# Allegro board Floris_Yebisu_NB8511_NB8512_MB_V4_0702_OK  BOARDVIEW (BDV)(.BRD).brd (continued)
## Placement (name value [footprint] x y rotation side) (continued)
CT28  cap  [C0201]  22.17 27.63 180 top
CT29  cap  [C0201]  24.26 27.63 0 top
CT30  CAP  [C0201]  25.91 23.44 90 bottom
CT31  CAP  [C0201]  31.37 24.58 0 top
CT32  CL10A226MQ8NRNC~~GRM188R60J226MEA0D~~JDK107BBJ226MA-T~~CC0603MRX5R5BB226  [C0603_L]  28.19 28.39 90 top
CT33  CL10A226MQ8NRNC~~GRM188R60J226MEA0D~~JDK107BBJ226MA-T~~CC0603MRX5R5BB226  [C0603_L]  29.49 28.39 90 top
CT34  CAP  [C0201]  29.06 29.08 180 bottom
CT35  CAP  [C0201]  29.06 28.57 180 bottom
CT36  CAP  [C0201]  24.36 22.55 180 bottom
CT37  CAP  [C0201]  27.76 24.97 0 bottom
CT38  CL10A226MQ8NRNC~~GRM188R60J226MEA0D~~JDK107BBJ226MA-T~~CC0603MRX5R5BB226  [C0603_L]  32.89 28.39 90 top
CT39  CL10A226MQ8NRNC~~GRM188R60J226MEA0D~~JDK107BBJ226MA-T~~CC0603MRX5R5BB226  [C0603_L]  31.49 28.39 90 top
CT40  CAP  [C0201]  31.62 28.27 90 bottom
CT41  CAP  [C0201]  27.73 22.78 0 bottom
CT42  CAP  [C0201]  25.14 23.95 180 bottom
CT43  CAP  [C0201]  23.11 23.95 180 bottom
CT44  CAP  [C0201]  32.13 28.27 90 bottom
CT45  CAP  [C0201]  27.56 24.2 270 bottom
CT46  C0201C0G180J500NTA~~GRM0335C1H180JA01D~~CC0201JRNPO9BN180  [C0201]  27.73 23.34 0 bottom
CT47  CAP  [C0201]  26.31 28.22 90 top
CT48  C0402X5R106M6R3NTC~~CL05A106MQ5NUNC~~GRM155R60J106ME44~~JMK105CBJ106MV-F  [C0402_0D8]  27.05 28.37 90 top
CT50  CAP  [C0201]  24.13 26.29 180 bottom
CT51  C0201C0G180J500NTA~~GRM0335C1H180JA01D~~CC0201JRNPO9BN180  [C0201]  24.13 25.73 180 bottom
CT52  C0402X5R106M6R3NTC~~CL05A106MQ5NUNC~~GRM155R60J106ME44~~JMK105CBJ106MV-F  [C0402_0D8]  25.78 28.78 90 bottom
CT54  C0201X5R104M6R3NTA~~0201X104M6R3NT  [C0201]  24.51 32.71 0 bottom
CT55  C0402X5R475M6R3NTC~~JMK105BBJ475MV-F+JDK105ABJ475MV~~CC0402MRX5R5BB475~~CL05A475MQ5NRNC~~GRM155R60J475ME87D  [C0402_0D65]  24.74 12.11 270 top
CT56  C0201X5R104M250NTJ  [C0201]  23.98 12.11 270 top
CT57  PSBD1DF40V3H  [DIODE_2D75X1D8X1D1]  19.66 15.39 0 top
CT58  C0603X5R106M250NTK~~CL10A106MA8NRNC~~GRM188R61E106MA73D~~TMK107BBJ106MA  [C0603_L]  25.91 12.16 270 top
CT59  C0603X5R106M250NTK~~CL10A106MA8NRNC~~GRM188R61E106MA73D~~TMK107BBJ106MA  [C0603_L]  27.28 12.16 270 top
CT60  C0603X5R106M250NTK~~CL10A106MA8NRNC~~GRM188R61E106MA73D~~TMK107BBJ106MA  [C0603_L]  18.54 12.27 270 top
CT61  C0201X7R102K250NTA+C0201X7R102K250NJA~~GRM033R71E102KA01D~~CC0201KRX7R8BB102  [C0201]  20.06 9.48 180 top
CT62  xxxxxx  [C0402]  12.7 22.93 180 bottom
CT63  xxxxxx  [C0402]  12.7 22.04 180 bottom
CT64  xxxxxx  [C0402]  12.44 16.96 180 top
CT65  xxxxxx  [C0402]  12.44 17.85 180 top
CT66  C0201X5R104M250NTJ  [C0201]  8.89 11.88 180 top
CT67  C0201X5R105M6R3NTX~~CL03A105MQ3CSNH~~GRM033R60J105MEA2D~~JMK063ABJ105MP+JDK063ABJ105MP~~CC0201MRX5R5BB105  [C0201_0D4]  13.84 8.2 0 top
CT68  xxxxxx  [C0402]  12.7 22.93 180 top
CT69  xxxxxx  [C0402]  12.7 22.04 180 top
CT70  xxxxxx  [C0402]  12.44 16.96 180 bottom
CT71  xxxxxx  [C0402]  12.44 17.85 180 bottom
CT72  C0201C0G101J500NTA~~GRM0335C1H101JA01D~~CC0201JRNPO9BN101  [C0201]  9.29 11.17 90 bottom
CT73  C0201C0G101J500NTA~~GRM0335C1H101JA01D~~CC0201JRNPO9BN101  [C0201]  9.29 10.13 270 bottom
CT74  C0201X5R104M250NTJ  [C0201]  11.12 14.42 270 top
CT75  C0603X5R106M250NTK~~CL10A106MA8NRNC~~GRM188R61E106MA73D~~TMK107BBJ106MA  [C0603_L]  13.59 14.3 270 top
CT76  C0201X5R104M250NTJ  [C0201]  12.65 14.42 270 top
CT77  C0603X5R106M250NTK~~CL10A106MA8NRNC~~GRM188R61E106MA73D~~TMK107BBJ106MA  [C0603_L]  14.88 14.3 270 top
CT78  C0201C0G470J250NTA~~GRM0335C1E470JD01D~~CC0201JRNPO8BN470  [C0201]  12.14 14.42 270 top
CT79  C0201C0G101J500NTA~~GRM0335C1H101JA01D~~CC0201JRNPO9BN101  [C0201]  10.31 8.63 0 bottom
CT80  C0201C0G101J500NTA~~GRM0335C1H101JA01D~~CC0201JRNPO9BN101  [C0201]  8.33 8.71 90 bottom
CT81  CC0201JRNPO9BN220~~C0201C0G220J500NTA  [C0201]  11.63 14.42 270 top
CT82  CL10A226MQ8NRNC~~GRM188R60J226MEA0D~~JDK107BBJ226MA-T~~CC0603MRX5R5BB226  [C0603_L]  34.44 26.13 0 top
CT83  CL10A226MQ8NRNC~~GRM188R60J226MEA0D~~JDK107BBJ226MA-T~~CC0603MRX5R5BB226  [C0603_L]  34.29 28.39 90 top
CU1  CC0201JRNPO8BN220~~GRM0335C1E220JD01  [C0201]  72.01 72.84 90 top
CU2  CC0201JRNPO8BN220~~GRM0335C1E220JD01  [C0201]  72.52 72.84 90 top
CU3  CC0201JRNPO8BN220~~GRM0335C1E220JD01  [C0201]  73.02 72.84 90 top
CU4  CC0201JRNPO8BN220~~GRM0335C1E220JD01  [C0201]  73.53 72.84 90 top
CU5  CC0201JRNPO8BN220~~GRM0335C1E220JD01  [C0201]  71.5 72.84 90 top
CU6  cap  [C0201]  63.37 71.83 90 bottom
CU7  cap  [C0201]  63.37 70.81 270 bottom
CU8  cap  [C0201]  58.16 44.4 270 bottom
CU9  cap  [C0201]  58.16 46.43 90 bottom
CU10  C0201X5R105M6R3NTX~~CL03A105MQ3CSNH~~GRM033R60J105MEA2D~~JMK063ABJ105MP+JDK063ABJ105MP~~CC0201MRX5R5BB105  [C0201_0D4]  55.95 62.94 270 bottom
CU11  C0201X5R105M6R3NTX~~CL03A105MQ3CSNH~~GRM033R60J105MEA2D~~JMK063ABJ105MP+JDK063ABJ105MP~~CC0201MRX5R5BB105  [C0201_0D4]  55.12 77.8 180 top
CU13  C0201X7R103K160NTA+C0201X7R103K160NJA~~GRM033R71C103KA01D~~CC0201KRX7R7BB103  [C0201]  57.15 58.62 0 bottom
CU14  C0201C0G270J250NTA~~GRM0335C1E270JD01D~~CC0201JRNPO8BN270  [C0201]  68.43 58.87 90 top
CU15  C0201C0G270J250NTA~~GRM0335C1E270JD01D~~CC0201JRNPO8BN270  [C0201]  69.85 61.29 180 top
CU16  C0201C0G270J250NTA~~GRM0335C1E270JD01D~~CC0201JRNPO8BN270  [C0201]  70.48 60.4 180 top
CU17  C0201C0G270J250NTA~~GRM0335C1E270JD01D~~CC0201JRNPO8BN270  [C0201]  70.99 61.67 90 top
CU18  C0201C0G2R0C250NTA~~GRM0335C1E2R0CD01D~~CC0201CRNPO9BN2R0  [C0201]  57.15 78.18 0 top
CU19  C0201C0G2R0C250NTA~~GRM0335C1E2R0CD01D~~CC0201CRNPO9BN2R0  [C0201]  58.42 83 0 top
CU20  C0201C0G2R0C250NTA~~GRM0335C1E2R0CD01D~~CC0201CRNPO9BN2R0  [C0201]  59.18 83.89 90 top
CU21  C0201C0G2R0C250NTA~~GRM0335C1E2R0CD01D~~CC0201CRNPO9BN2R0  [C0201]  57.66 81.48 90 top
CU22  C0201C0G2R0C250NTA~~GRM0335C1E2R0CD01D~~CC0201CRNPO9BN2R0  [C0201]  71.94 62.94 270 top
CU23  C0201X5R224M6R3NTJ~~GRM033R60J224ME15D~~CC0201MRX5R5BB224  [C0201]  70.74 37.41 90 bottom
CU24  C0201X5R224M6R3NTJ~~GRM033R60J224ME15D~~CC0201MRX5R5BB224  [C0201]  71.25 37.41 90 bottom
CU25  C0201X5R224M6R3NTJ~~GRM033R60J224ME15D~~CC0201MRX5R5BB224  [C0201]  72.39 37.41 90 bottom
CU26  C0201X5R224M6R3NTJ~~GRM033R60J224ME15D~~CC0201MRX5R5BB224  [C0201]  71.88 37.41 90 bottom
CU27  C0201X5R224M6R3NTJ~~GRM033R60J224ME15D~~CC0201MRX5R5BB224  [C0201]  68.45 37.41 270 bottom
CU28  C0201X5R224M6R3NTJ~~GRM033R60J224ME15D~~CC0201MRX5R5BB224  [C0201]  68.96 37.41 270 bottom
CU29  C0201X5R224M6R3NTJ~~GRM033R60J224ME15D~~CC0201MRX5R5BB224  [C0201]  70.1 37.41 270 bottom
CU30  C0201X5R224M6R3NTJ~~GRM033R60J224ME15D~~CC0201MRX5R5BB224  [C0201]  69.59 37.41 270 bottom
CU31  CC0201KRX5R7BB104~~C0201X5R104M160NTA  [C0201]  55.12 76.27 180 top
CU32  C0201X7R472K100NTA+C0201X7R472K100NJA~~GRM033R71A472KA01D~~CC0201KRX7R6BB472  [C0201]  79.5 37.92 270 bottom
CU33  C0201X5R104M6R3NTA~~0201X104M6R3NT  [C0201]  125.98 89.86 0 top
CU34  C0201C0G101J500NTA~~GRM0335C1H101JA01D~~CC0201JRNPO9BN101  [C0201]  128.27 89.86 0 top
CU35  C0201C0G101J500NTA~~GRM0335C1H101JA01D~~CC0201JRNPO9BN101  [C0201]  78.74 37.54 180 bottom
CU36  C0201C0G101J500NTA~~GRM0335C1H101JA01D~~CC0201JRNPO9BN101  [C0201]  66.34 51.94 0 top
CU37  C0201X5R105M6R3NTX~~CL03A105MQ3CSNH~~GRM033R60J105MEA2D~~JMK063ABJ105MP+JDK063ABJ105MP~~CC0201MRX5R5BB105  [C0201_0D4]  45.72 3.76 90 top
CU38  C0201X5R222K250NTA~~CC0201KRX5R8BB222  [C0201]  66.67 62.99 180 top
CU39  C0201C0G101J500NTA~~GRM0335C1H101JA01D~~CC0201JRNPO9BN101  [C0201]  57.17 64.26 0 bottom
CU40  C0201X5R105M6R3NTX~~CL03A105MQ3CSNH~~GRM033R60J105MEA2D~~JMK063ABJ105MP+JDK063ABJ105MP~~CC0201MRX5R5BB105  [C0201_0D4]  112.9 36.78 270 bottom
CU41  GRM155R60J225KE95~~CL05A225KQ5NNNC  [C0402]  63.63 59.13 0 top
CU42  C0201X5R105M6R3NTX~~CL03A105MQ3CSNH~~GRM033R60J105MEA2D~~JMK063ABJ105MP+JDK063ABJ105MP~~CC0201MRX5R5BB105  [C0201_0D4]  65.5 48.36 0 top
CU43  CL10A226MQ8NRNC~~GRM188R60J226MEA0D~~JDK107BBJ226MA-T~~CC0603MRX5R5BB226  [C0603_L]  64.77 44.4 270 top
CU44  CL10A226MQ8NRNC~~GRM188R60J226MEA0D~~JDK107BBJ226MA-T~~CC0603MRX5R5BB226  [C0603_L]  63.37 44.4 270 top
CU45  C0201X5R105M6R3NTX~~CL03A105MQ3CSNH~~GRM033R60J105MEA2D~~JMK063ABJ105MP+JDK063ABJ105MP~~CC0201MRX5R5BB105  [C0201_0D4]  70.48 55.78 0 top
CU46  C0201X5R105M6R3NTX~~CL03A105MQ3CSNH~~GRM033R60J105MEA2D~~JMK063ABJ105MP+JDK063ABJ105MP~~CC0201MRX5R5BB105  [C0201_0D4]  69.72 51.38 90 top
CU47  C0201X5R105M6R3NTX~~CL03A105MQ3CSNH~~GRM033R60J105MEA2D~~JMK063ABJ105MP+JDK063ABJ105MP~~CC0201MRX5R5BB105  [C0201_0D4]  72.26 59.64 0 top
CU48  C0201X5R105M6R3NTX~~CL03A105MQ3CSNH~~GRM033R60J105MEA2D~~JMK063ABJ105MP+JDK063ABJ105MP~~CC0201MRX5R5BB105  [C0201_0D4]  68.37 50.98 180 top
CU49  C0402X5R475M6R3NTC~~JMK105BBJ475MV-F+JDK105ABJ475MV~~CC0402MRX5R5BB475~~CL05A475MQ5NRNC~~GRM155R60J475ME87D  [C0402_0D65]  63.88 57.99 0 top
CU50  C0201X5R105M6R3NTX~~CL03A105MQ3CSNH~~GRM033R60J105MEA2D~~JMK063ABJ105MP+JDK063ABJ105MP~~CC0201MRX5R5BB105  [C0201_0D4]  71.88 57.99 0 top
CU51  C0201X5R105M6R3NTX~~CL03A105MQ3CSNH~~GRM033R60J105MEA2D~~JMK063ABJ105MP+JDK063ABJ105MP~~CC0201MRX5R5BB105  [C0201_0D4]  70.1 57.86 0 top
CU52  C0201X5R104M6R3NTA~~0201X104M6R3NT  [C0201]  66.55 57.93 270 top
CU53  C0201X5R105M6R3NTX~~CL03A105MQ3CSNH~~GRM033R60J105MEA2D~~JMK063ABJ105MP+JDK063ABJ105MP~~CC0201MRX5R5BB105  [C0201_0D4]  69.98 55.19 0 top
CU54  C0201X5R104M6R3NTA~~0201X104M6R3NT  [C0201]  71.5 56.84 0 top
CU55  C0201X5R105M6R3NTX~~CL03A105MQ3CSNH~~GRM033R60J105MEA2D~~JMK063ABJ105MP+JDK063ABJ105MP~~CC0201MRX5R5BB105  [C0201_0D4]  115.44 36.65 90 bottom
CU56  C0201X5R105M6R3NTX~~CL03A105MQ3CSNH~~GRM033R60J105MEA2D~~JMK063ABJ105MP+JDK063ABJ105MP~~CC0201MRX5R5BB105  [C0201_0D4]  81.72 37.92 270 bottom
CU57  C0201X5R105M6R3NTX~~CL03A105MQ3CSNH~~GRM033R60J105MEA2D~~JMK063ABJ105MP+JDK063ABJ105MP~~CC0201MRX5R5BB105  [C0201_0D4]  82.23 37.92 270 bottom
CU58  C0201X5R105M6R3NTX~~CL03A105MQ3CSNH~~GRM033R60J105MEA2D~~JMK063ABJ105MP+JDK063ABJ105MP~~CC0201MRX5R5BB105  [C0201_0D4]  105.54 58.87 90 top
CU59  C0201X5R105M6R3NTX~~CL03A105MQ3CSNH~~GRM033R60J105MEA2D~~JMK063ABJ105MP+JDK063ABJ105MP~~CC0201MRX5R5BB105  [C0201_0D4]  75.69 59.18 90 top
CU60  C0201X5R105M6R3NTX~~CL03A105MQ3CSNH~~GRM033R60J105MEA2D~~JMK063ABJ105MP+JDK063ABJ105MP~~CC0201MRX5R5BB105  [C0201_0D4]  75.82 58.06 180 top
CU61  C0201X5R105M6R3NTX~~CL03A105MQ3CSNH~~GRM033R60J105MEA2D~~JMK063ABJ105MP+JDK063ABJ105MP~~CC0201MRX5R5BB105  [C0201_0D4]  75.82 57.48 180 top
CU62  C0201X5R105M6R3NTX~~CL03A105MQ3CSNH~~GRM033R60J105MEA2D~~JMK063ABJ105MP+JDK063ABJ105MP~~CC0201MRX5R5BB105  [C0201_0D4]  77.47 59.2 90 top
CU63  C0201X5R105M6R3NTX~~CL03A105MQ3CSNH~~GRM033R60J105MEA2D~~JMK063ABJ105MP+JDK063ABJ105MP~~CC0201MRX5R5BB105  [C0201_0D4]  76.5 59.36 90 top
CU64  C0201X5R105M6R3NTX~~CL03A105MQ3CSNH~~GRM033R60J105MEA2D~~JMK063ABJ105MP+JDK063ABJ105MP~~CC0201MRX5R5BB105  [C0201_0D4]  83.82 47.06 0 top
CU65  C0201C0G120J250NTA~~GRM0335C1E120JA01D~~CC0201JRNPO8BN120  [C0201]  83.18 45.34 270 top
CU66  C0201C0G101J250NTA+C0201C0G101J250NJA~~GRM0335C1E101JD01D~~CC0201JRNPO8BN101  [C0201]  79.51 46.07 270 top
CU67  C0402X5R106M6R3NTC~~CL05A106MQ5NUNC~~GRM155R60J106ME44~~JMK105CBJ106MV-F  [C0402_0D8]  104.93 42.95 0 top
CU68  C0402X5R106M6R3NTC~~CL05A106MQ5NUNC~~GRM155R60J106ME44~~JMK105CBJ106MV-F  [C0402_0D8]  82.8 46.33 180 top
CU69  C0402X5R106M6R3NTC~~CL05A106MQ5NUNC~~GRM155R60J106ME44~~JMK105CBJ106MV-F  [C0402_0D8]  80.01 56.97 180 top
CU70  C0402X5R106M6R3NTC~~CL05A106MQ5NUNC~~GRM155R60J106ME44~~JMK105CBJ106MV-F  [C0402_0D8]  104.65 56.59 90 top
CU71  C0402X5R106M6R3NTC~~CL05A106MQ5NUNC~~GRM155R60J106ME44~~JMK105CBJ106MV-F  [C0402_0D8]  106.17 56.59 90 top
CU72  C0402X5R106M6R3NTC~~CL05A106MQ5NUNC~~GRM155R60J106ME44~~JMK105CBJ106MV-F  [C0402_0D8]  82.47 47.7 270 top
CU73  C0402X5R106M6R3NTC~~CL05A106MQ5NUNC~~GRM155R60J106ME44~~JMK105CBJ106MV-F  [C0402_0D8]  99.79 48.59 270 top
CU74  C0402X5R106M6R3NTC~~CL05A106MQ5NUNC~~GRM155R60J106ME44~~JMK105CBJ106MV-F  [C0402_0D8]  84.83 47.7 90 top
CU75  C0402X5R106M6R3NTC~~CL05A106MQ5NUNC~~GRM155R60J106ME44~~JMK105CBJ106MV-F  [C0402_0D8]  122.05 55.7 90 bottom
CU76  C0402X5R106M6R3NTC~~CL05A106MQ5NUNC~~GRM155R60J106ME44~~JMK105CBJ106MV-F  [C0402_0D8]  84.71 45.79 270 top
CU77  C0402X5R106M6R3NTC~~CL05A106MQ5NUNC~~GRM155R60J106ME44~~JMK105CBJ106MV-F  [C0402_0D8]  81.53 47.7 270 top
CU78  C0402X5R106M6R3NTC~~CL05A106MQ5NUNC~~GRM155R60J106ME44~~JMK105CBJ106MV-F  [C0402_0D8]  100.71 48.59 270 top
CU79  C0402X5R106M6R3NTC~~CL05A106MQ5NUNC~~GRM155R60J106ME44~~JMK105CBJ106MV-F  [C0402_0D8]  107.19 56.59 90 top
CU80  C0402X5R106M6R3NTC~~CL05A106MQ5NUNC~~GRM155R60J106ME44~~JMK105CBJ106MV-F  [C0402_0D8]  78.23 57.35 270 top
CU81  CL10A226MQ8NRNC~~GRM188R60J226MEA0D~~JDK107BBJ226MA-T~~CC0603MRX5R5BB226  [C0603_L]  126.11 46.43 0 bottom
CU82  CL10A226MQ8NRNC~~GRM188R60J226MEA0D~~JDK107BBJ226MA-T~~CC0603MRX5R5BB226  [C0603_L]  126.11 43.63 0 bottom
CU83  C0402X5R106M6R3NTC~~CL05A106MQ5NUNC~~GRM155R60J106ME44~~JMK105CBJ106MV-F  [C0402_0D8]  80.85 46.25 0 top
CU84  C0402X5R106M6R3NTC~~CL05A106MQ5NUNC~~GRM155R60J106ME44~~JMK105CBJ106MV-F  [C0402_0D8]  101.98 56.59 90 top
CU85  C0402X5R106M6R3NTC~~CL05A106MQ5NUNC~~GRM155R60J106ME44~~JMK105CBJ106MV-F  [C0402_0D8]  119 55.7 90 bottom
CU86  C0402X5R106M6R3NTC~~CL05A106MQ5NUNC~~GRM155R60J106ME44~~JMK105CBJ106MV-F  [C0402_0D8]  120.01 55.7 90 bottom
CU87  C0402X5R106M6R3NTC~~CL05A106MQ5NUNC~~GRM155R60J106ME44~~JMK105CBJ106MV-F  [C0402_0D8]  103.25 56.59 90 top
CU88  C0402X5R106M6R3NTC~~CL05A106MQ5NUNC~~GRM155R60J106ME44~~JMK105CBJ106MV-F  [C0402_0D8]  100.07 55.83 90 top
CU89  C0402X5R106M6R3NTC~~CL05A106MQ5NUNC~~GRM155R60J106ME44~~JMK105CBJ106MV-F  [C0402_0D8]  101.04 55.83 90 top
CU90  C0402X5R106M6R3NTC~~CL05A106MQ5NUNC~~GRM155R60J106ME44~~JMK105CBJ106MV-F  [C0402_0D8]  85.62 45.79 270 top
CU91  C0402X5R106M6R3NTC~~CL05A106MQ5NUNC~~GRM155R60J106ME44~~JMK105CBJ106MV-F  [C0402_0D8]  100.38 43.05 180 top
CU92  C0402X5R106M6R3NTC~~CL05A106MQ5NUNC~~GRM155R60J106ME44~~JMK105CBJ106MV-F  [C0402_0D8]  79.37 58.62 90 top
CU93  C0402X5R106M6R3NTC~~CL05A106MQ5NUNC~~GRM155R60J106ME44~~JMK105CBJ106MV-F  [C0402_0D8]  81.53 58.24 270 top
CU94  C0402X5R106M6R3NTC~~CL05A106MQ5NUNC~~GRM155R60J106ME44~~JMK105CBJ106MV-F  [C0402_0D8]  121.03 55.7 90 bottom
CU95  CL10A226MQ8NRNC~~GRM188R60J226MEA0D~~JDK107BBJ226MA-T~~CC0603MRX5R5BB226  [C0603_L]  126.11 46.43 0 top
CU96  CL10A226MQ8NRNC~~GRM188R60J226MEA0D~~JDK107BBJ226MA-T~~CC0603MRX5R5BB226  [C0603_L]  126.11 43.63 0 top
CU97  C0201X5R105M6R3NTX~~CL03A105MQ3CSNH~~GRM033R60J105MEA2D~~JMK063ABJ105MP+JDK063ABJ105MP~~CC0201MRX5R5BB105  [C0201_0D4]  83.46 38.28 180 bottom
CU98  C0201X5R105M6R3NTX~~CL03A105MQ3CSNH~~GRM033R60J105MEA2D~~JMK063ABJ105MP+JDK063ABJ105MP~~CC0201MRX5R5BB105  [C0201_0D4]  83.46 37.77 180 bottom
CU99  C0201X5R105M6R3NTX~~CL03A105MQ3CSNH~~GRM033R60J105MEA2D~~JMK063ABJ105MP+JDK063ABJ105MP~~CC0201MRX5R5BB105  [C0201_0D4]  84.58 37.67 180 bottom
CU100  C0201X5R105M6R3NTX~~CL03A105MQ3CSNH~~GRM033R60J105MEA2D~~JMK063ABJ105MP+JDK063ABJ105MP~~CC0201MRX5R5BB105  [C0201_0D4]  84.58 37.16 180 bottom
CU101  C0402X5R106M6R3NTC~~CL05A106MQ5NUNC~~GRM155R60J106ME44~~JMK105CBJ106MV-F  [C0402_0D8]  85.79 37.03 270 bottom
CU102  C0402X5R106M6R3NTC~~CL05A106MQ5NUNC~~GRM155R60J106ME44~~JMK105CBJ106MV-F  [C0402_0D8]  88.49 46.78 90 top
CU103  C0402X5R106M6R3NTC~~CL05A106MQ5NUNC~~GRM155R60J106ME44~~JMK105CBJ106MV-F  [C0402_0D8]  86.74 37.03 270 bottom
CU104  C0201C0G120J250NTA~~GRM0335C1E120JA01D~~CC0201JRNPO8BN120  [C0201]  87.76 46.73 90 top
CU105  C0201C0G101J250NTA+C0201C0G101J250NJA~~GRM0335C1E101JD01D~~CC0201JRNPO8BN101  [C0201]  86.84 45.36 270 top
CU106  C0201X5R105M6R3NTX~~CL03A105MQ3CSNH~~GRM033R60J105MEA2D~~JMK063ABJ105MP+JDK063ABJ105MP~~CC0201MRX5R5BB105  [C0201_0D4]  79.75 63.19 90 top
CU107  C0201X5R105M6R3NTX~~CL03A105MQ3CSNH~~GRM033R60J105MEA2D~~JMK063ABJ105MP+JDK063ABJ105MP~~CC0201MRX5R5BB105  [C0201_0D4]  80.44 59.76 270 top
CU108  C0201X5R105M6R3NTX~~CL03A105MQ3CSNH~~GRM033R60J105MEA2D~~JMK063ABJ105MP+JDK063ABJ105MP~~CC0201MRX5R5BB105  [C0201_0D4]  105.76 48.41 0 top
CU109  C0201X5R105M6R3NTX~~CL03A105MQ3CSNH~~GRM033R60J105MEA2D~~JMK063ABJ105MP+JDK063ABJ105MP~~CC0201MRX5R5BB105  [C0201_0D4]  77.34 46.33 0 top
CU110  C0201X5R105M6R3NTX~~CL03A105MQ3CSNH~~GRM033R60J105MEA2D~~JMK063ABJ105MP+JDK063ABJ105MP~~CC0201MRX5R5BB105  [C0201_0D4]  97.92 43 90 top
CU111  C0201X5R105M6R3NTX~~CL03A105MQ3CSNH~~GRM033R60J105MEA2D~~JMK063ABJ105MP+JDK063ABJ105MP~~CC0201MRX5R5BB105  [C0201_0D4]  104.06 48.08 0 top
CU112  C0201C0G120J250NTA~~GRM0335C1E120JA01D~~CC0201JRNPO8BN120  [C0201]  103.38 49.1 180 top
CU113  C0201C0G101J250NTA+C0201C0G101J250NJA~~GRM0335C1E101JD01D~~CC0201JRNPO8BN101  [C0201]  103.38 49.6 180 top
CU114  C0402X5R106M6R3NTC~~CL05A106MQ5NUNC~~GRM155R60J106ME44~~JMK105CBJ106MV-F  [C0402_0D8]  78.74 43.86 0 top
CU115  C0402X5R106M6R3NTC~~CL05A106MQ5NUNC~~GRM155R60J106ME44~~JMK105CBJ106MV-F  [C0402_0D8]  78.74 42.95 0 top
CU116  C0402X5R106M6R3NTC~~CL05A106MQ5NUNC~~GRM155R60J106ME44~~JMK105CBJ106MV-F  [C0402_0D8]  96.54 43.33 90 top
CU117  C0402X5R106M6R3NTC~~CL05A106MQ5NUNC~~GRM155R60J106ME44~~JMK105CBJ106MV-F  [C0402_0D8]  80.26 43.38 90 top
CU118  C0402X5R106M6R3NTC~~CL05A106MQ5NUNC~~GRM155R60J106ME44~~JMK105CBJ106MV-F  [C0402_0D8]  95.12 46.68 270 top
CU119  C0402X5R106M6R3NTC~~CL05A106MQ5NUNC~~GRM155R60J106ME44~~JMK105CBJ106MV-F  [C0402_0D8]  84.45 43.38 90 top
CU120  C0402X5R106M6R3NTC~~CL05A106MQ5NUNC~~GRM155R60J106ME44~~JMK105CBJ106MV-F  [C0402_0D8]  70.05 46.71 180 top
CU121  C0402X5R106M6R3NTC~~CL05A106MQ5NUNC~~GRM155R60J106ME44~~JMK105CBJ106MV-F  [C0402_0D8]  86.21 44.32 180 top
CU122  C0402X5R106M6R3NTC~~CL05A106MQ5NUNC~~GRM155R60J106ME44~~JMK105CBJ106MV-F  [C0402_0D8]  69.72 44.52 180 top
CU123  C0402X5R106M6R3NTC~~CL05A106MQ5NUNC~~GRM155R60J106ME44~~JMK105CBJ106MV-F  [C0402_0D8]  97.08 34.62 0 top
CU124  C0402X5R106M6R3NTC~~CL05A106MQ5NUNC~~GRM155R60J106ME44~~JMK105CBJ106MV-F  [C0402_0D8]  77.21 47.06 0 top
CU125  C0402X5R106M6R3NTC~~CL05A106MQ5NUNC~~GRM155R60J106ME44~~JMK105CBJ106MV-F  [C0402_0D8]  93.34 43 0 top
CU126  C0402X5R106M6R3NTC~~CL05A106MQ5NUNC~~GRM155R60J106ME44~~JMK105CBJ106MV-F  [C0402_0D8]  85.85 43 180 top
CU127  C0402X5R106M6R3NTC~~CL05A106MQ5NUNC~~GRM155R60J106ME44~~JMK105CBJ106MV-F  [C0402_0D8]  90.19 46.91 180 top
CU128  C0402X5R106M6R3NTC~~CL05A106MQ5NUNC~~GRM155R60J106ME44~~JMK105CBJ106MV-F  [C0402_0D8]  70.1 47.65 180 top
CU129  C0402X5R106M6R3NTC~~CL05A106MQ5NUNC~~GRM155R60J106ME44~~JMK105CBJ106MV-F  [C0402_0D8]  90.19 47.83 180 top
CU130  C0402X5R106M6R3NTC~~CL05A106MQ5NUNC~~GRM155R60J106ME44~~JMK105CBJ106MV-F  [C0402_0D8]  93.24 46.66 270 top
CU131  C0402X5R106M6R3NTC~~CL05A106MQ5NUNC~~GRM155R60J106ME44~~JMK105CBJ106MV-F  [C0402_0D8]  94.16 46.66 270 top
CU132  C0402X5R106M6R3NTC~~CL05A106MQ5NUNC~~GRM155R60J106ME44~~JMK105CBJ106MV-F  [C0402_0D8]  95.17 42.97 180 top
CU133  C0402X5R106M6R3NTC~~CL05A106MQ5NUNC~~GRM155R60J106ME44~~JMK105CBJ106MV-F  [C0402_0D8]  69.77 45.77 180 top
CU134  C0402X5R106M6R3NTC~~CL05A106MQ5NUNC~~GRM155R60J106ME44~~JMK105CBJ106MV-F  [C0402_0D8]  105.71 49.12 0 top
CU135  C0402X5R106M6R3NTC~~CL05A106MQ5NUNC~~GRM155R60J106ME44~~JMK105CBJ106MV-F  [C0402_0D8]  70.1 48.59 180 top
CU136  C0402X5R106M6R3NTC~~CL05A106MQ5NUNC~~GRM155R60J106ME44~~JMK105CBJ106MV-F  [C0402_0D8]  70.03 43.58 180 top
CU137  C0402X5R106M6R3NTC~~CL05A106MQ5NUNC~~GRM155R60J106ME44~~JMK105CBJ106MV-F  [C0402_0D8]  103.38 50.34 180 top
CU138  CL10A226MQ8NRNC~~GRM188R60J226MEA0D~~JDK107BBJ226MA-T~~CC0603MRX5R5BB226  [C0603_L]  88.26 33.91 180 top
CU139  CL10A226MQ8NRNC~~GRM188R60J226MEA0D~~JDK107BBJ226MA-T~~CC0603MRX5R5BB226  [C0603_L]  97.15 31.44 0 top
CU140  CL10A226MQ8NRNC~~GRM188R60J226MEA0D~~JDK107BBJ226MA-T~~CC0603MRX5R5BB226  [C0603_L]  97.03 34.62 0 bottom
CU141  CL10A226MQ8NRNC~~GRM188R60J226MEA0D~~JDK107BBJ226MA-T~~CC0603MRX5R5BB226  [C0603_L]  97.15 32.74 0 top
CU142  C0201X5R105M6R3NTX~~CL03A105MQ3CSNH~~GRM033R60J105MEA2D~~JMK063ABJ105MP+JDK063ABJ105MP~~CC0201MRX5R5BB105  [C0201_0D4]  85.93 60.42 90 top
CU143  C0201X5R105M6R3NTX~~CL03A105MQ3CSNH~~GRM033R60J105MEA2D~~JMK063ABJ105MP+JDK063ABJ105MP~~CC0201MRX5R5BB105  [C0201_0D4]  96.44 63.19 270 top
CU144  C0201X5R105M6R3NTX~~CL03A105MQ3CSNH~~GRM033R60J105MEA2D~~JMK063ABJ105MP+JDK063ABJ105MP~~CC0201MRX5R5BB105  [C0201_0D4]  107.88 60.75 90 top
CU145  C0201X5R105M6R3NTX~~CL03A105MQ3CSNH~~GRM033R60J105MEA2D~~JMK063ABJ105MP+JDK063ABJ105MP~~CC0201MRX5R5BB105  [C0201_0D4]  85.01 60.42 90 top
CU146  C0201X5R105M6R3NTX~~CL03A105MQ3CSNH~~GRM033R60J105MEA2D~~JMK063ABJ105MP+JDK063ABJ105MP~~CC0201MRX5R5BB105  [C0201_0D4]  82.29 59.64 270 top
CU147  C0201X5R105M6R3NTX~~CL03A105MQ3CSNH~~GRM033R60J105MEA2D~~JMK063ABJ105MP+JDK063ABJ105MP~~CC0201MRX5R5BB105  [C0201_0D4]  82.68 63.19 270 top
CU148  C0402X5R106M6R3NTC~~CL05A106MQ5NUNC~~GRM155R60J106ME44~~JMK105CBJ106MV-F  [C0402_0D8]  89.15 59.64 90 top
CU149  C0402X5R106M6R3NTC~~CL05A106MQ5NUNC~~GRM155R60J106ME44~~JMK105CBJ106MV-F  [C0402_0D8]  110.31 61.67 0 top
CU150  C0201C0G120J250NTA~~GRM0335C1E120JA01D~~CC0201JRNPO8BN120  [C0201]  90.93 63.19 270 top
CU151  C0201C0G101J250NTA+C0201C0G101J250NJA~~GRM0335C1E101JD01D~~CC0201JRNPO8BN101  [C0201]  101.85 63.19 270 top
CU152  C0402X5R106M6R3NTC~~CL05A106MQ5NUNC~~GRM155R60J106ME44~~JMK105CBJ106MV-F  [C0402_0D8]  86.87 59.38 0 top
CU153  C0402X5R106M6R3NTC~~CL05A106MQ5NUNC~~GRM155R60J106ME44~~JMK105CBJ106MV-F  [C0402_0D8]  100.33 59.38 90 top
CU154  C0402X5R106M6R3NTC~~CL05A106MQ5NUNC~~GRM155R60J106ME44~~JMK105CBJ106MV-F  [C0402_0D8]  92.2 59.64 0 top
CU155  C0402X5R106M6R3NTC~~CL05A106MQ5NUNC~~GRM155R60J106ME44~~JMK105CBJ106MV-F  [C0402_0D8]  93.98 59.64 180 top
CU156  C0402X5R106M6R3NTC~~CL05A106MQ5NUNC~~GRM155R60J106ME44~~JMK105CBJ106MV-F  [C0402_0D8]  90.17 59.64 90 top
CU157  C0402X5R106M6R3NTC~~CL05A106MQ5NUNC~~GRM155R60J106ME44~~JMK105CBJ106MV-F  [C0402_0D8]  99.19 59.41 90 top
CU158  C0402X5R106M6R3NTC~~CL05A106MQ5NUNC~~GRM155R60J106ME44~~JMK105CBJ106MV-F  [C0402_0D8]  110.11 59.64 270 top
CU159  C0402X5R106M6R3NTC~~CL05A106MQ5NUNC~~GRM155R60J106ME44~~JMK105CBJ106MV-F  [C0402_0D8]  84.96 59.26 180 top
CU160  C0402X5R106M6R3NTC~~CL05A106MQ5NUNC~~GRM155R60J106ME44~~JMK105CBJ106MV-F  [C0402_0D8]  95.88 59.38 0 top
CU161  C0402X5R106M6R3NTC~~CL05A106MQ5NUNC~~GRM155R60J106ME44~~JMK105CBJ106MV-F  [C0402_0D8]  97.66 59.38 180 top
CU162  C0201C0G150J250NTA~~GRM0335C1E150JA01D~~CC0201JRNPO8BN150  [C0201]  102.06 43.13 90 top
CU163  C0201C0G150J250NTA~~GRM0335C1E150JA01D~~CC0201JRNPO8BN150  [C0201]  106.55 42.87 0 top
CU164  C0201C0G150J250NTA~~GRM0335C1E150JA01D~~CC0201JRNPO8BN150  [C0201]  108.84 42.87 180 top
CU165  C0201C0G150J250NTA~~GRM0335C1E150JA01D~~CC0201JRNPO8BN150  [C0201]  70.05 42.87 180 top
CU166  C0201C0G150J250NTA~~GRM0335C1E150JA01D~~CC0201JRNPO8BN150  [C0201]  95.48 48.13 0 top
CU167  C0201C0G150J250NTA~~GRM0335C1E150JA01D~~CC0201JRNPO8BN150  [C0201]  82.29 43 90 top
CU168  C0201X5R104M6R3NTA~~0201X104M6R3NT  [C0201]  105.41 34.24 180 bottom
CU169  C0201X5R104M6R3NTA~~0201X104M6R3NT  [C0201]  69.59 71.04 180 bottom
CU170  C0201X7R472K100NTA+C0201X7R472K100NJA~~GRM033R71A472KA01D~~CC0201KRX7R6BB472  [C0201]  59.84 64.34 0 bottom
CU171  C0201X5R105M6R3NTX~~CL03A105MQ3CSNH~~GRM033R60J105MEA2D~~JMK063ABJ105MP+JDK063ABJ105MP~~CC0201MRX5R5BB105  [C0201_0D4]  70.99 54.18 0 top
CV1  C0402X5R475M6R3NTC~~JMK105BBJ475MV-F+JDK105ABJ475MV~~CC0402MRX5R5BB475~~CL05A475MQ5NRNC~~GRM155R60J475ME87D  [C0402_0D65]  165.3 90.6 0 top
CV2  C0402X5R475M6R3NTC~~JMK105BBJ475MV-F+JDK105ABJ475MV~~CC0402MRX5R5BB475~~CL05A475MQ5NRNC~~GRM155R60J475ME87D  [C0402_0D65]  166.86 79.97 0 bottom
CV3  C0402X5R106M6R3NTC~~CL05A106MQ5NUNC~~GRM155R60J106ME44~~JMK105CBJ106MV-F  [C0402_0D8]  156.34 76.15 90 top
CV4  C0402X5R106M6R3NTC~~CL05A106MQ5NUNC~~GRM155R60J106ME44~~JMK105CBJ106MV-F  [C0402_0D8]  158.38 76.6 180 top
CV5  CL10A226MQ8NRNC~~GRM188R60J226MEA0D~~JDK107BBJ226MA-T~~CC0603MRX5R5BB226  [C0603_L]  167 81.16 0 bottom
CV6  C0201X5R224M6R3NTJ~~GRM033R60J224ME15D~~CC0201MRX5R5BB224  [C0201]  145.18 76.96 0 top
CV7  C0201X5R224M6R3NTJ~~GRM033R60J224ME15D~~CC0201MRX5R5BB224  [C0201]  145.18 76.45 0 top
CV8  C0201X5R224M6R3NTJ~~GRM033R60J224ME15D~~CC0201MRX5R5BB224  [C0201]  143.91 78.56 0 top
CV9  C0201X5R224M6R3NTJ~~GRM033R60J224ME15D~~CC0201MRX5R5BB224  [C0201]  143.91 78.05 0 top
CV10  C0201X5R105M6R3NTX~~CL03A105MQ3CSNH~~GRM033R60J105MEA2D~~JMK063ABJ105MP+JDK063ABJ105MP~~CC0201MRX5R5BB105  [C0201_0D4]  151.38 76.78 180 top
CV11  C0402X5R475M6R3NTC~~JMK105BBJ475MV-F+JDK105ABJ475MV~~CC0402MRX5R5BB475~~CL05A475MQ5NRNC~~GRM155R60J475ME87D  [C0402_0D65]  161.34 84.77 0 bottom
CV12  CL10A226MQ8NRNC~~GRM188R60J226MEA0D~~JDK107BBJ226MA-T~~CC0603MRX5R5BB226  [C0603_L]  161.57 86.84 0 bottom
CV13  C0201X5R224M6R3NTJ~~GRM033R60J224ME15D~~CC0201MRX5R5BB224  [C0201]  143.92 79.75 0 top
CV14  C0201X5R224M6R3NTJ~~GRM033R60J224ME15D~~CC0201MRX5R5BB224  [C0201]  143.92 80.26 0 top
CV15  C0201X5R105M6R3NTX~~CL03A105MQ3CSNH~~GRM033R60J105MEA2D~~JMK063ABJ105MP+JDK063ABJ105MP~~CC0201MRX5R5BB105  [C0201_0D4]  157.19 75.76 270 top
CV16  C0402X5R475M6R3NTC~~JMK105BBJ475MV-F+JDK105ABJ475MV~~CC0402MRX5R5BB475~~CL05A475MQ5NRNC~~GRM155R60J475ME87D  [C0402_0D65]  165.3 89.68 0 top
CV17  C0201X5R104M6R3NTA~~0201X104M6R3NT  [C0201]  132.33 51.83 270 bottom
CV18  C0201X5R105M6R3NTX~~CL03A105MQ3CSNH~~GRM033R60J105MEA2D~~JMK063ABJ105MP+JDK063ABJ105MP~~CC0201MRX5R5BB105  [C0201_0D4]  159.51 79.12 135 top
CV19  C0201X5R105M6R3NTX~~CL03A105MQ3CSNH~~GRM033R60J105MEA2D~~JMK063ABJ105MP+JDK063ABJ105MP~~CC0201MRX5R5BB105  [C0201_0D4]  159.41 78.41 135 top
CV20  C0201X5R105M6R3NTX~~CL03A105MQ3CSNH~~GRM033R60J105MEA2D~~JMK063ABJ105MP+JDK063ABJ105MP~~CC0201MRX5R5BB105  [C0201_0D4]  153.8 77.54 270 top
CV21  C0402X5R106M6R3NTC~~CL05A106MQ5NUNC~~GRM155R60J106ME44~~JMK105CBJ106MV-F  [C0402_0D8]  155.41 78.62 90 top
CV22  C0201C0G330J250NTA+C0201C0G330J250NJA~~GRM0335C1E330JD01~~CC0201JRNPO8BN330  [C0201]  157.88 80.48 180 top
CV23  C0402X5R475M6R3NTC~~JMK105BBJ475MV-F+JDK105ABJ475MV~~CC0402MRX5R5BB475~~CL05A475MQ5NRNC~~GRM155R60J475ME87D  [C0402_0D65]  156.38 78.62 90 top
CV24  C0201X5R104M6R3NTA~~0201X104M6R3NT  [C0201]  131.97 56.94 90 bottom
CV25  C0402X5R106M6R3NTC~~CL05A106MQ5NUNC~~GRM155R60J106ME44~~JMK105CBJ106MV-F  [C0402_0D8]  161.35 85.71 0 bottom
CV26  C0201X5R224M6R3NTJ~~GRM033R60J224ME15D~~CC0201MRX5R5BB224  [C0201]  150.2 79.71 270 top
CV27  C0201X5R224M6R3NTJ~~GRM033R60J224ME15D~~CC0201MRX5R5BB224  [C0201]  150.73 79.71 270 top
CV28  C0201X5R104M6R3NTA~~0201X104M6R3NT  [C0201]  129.92 87.09 270 top
CV29  C0201X5R104M6R3NTA~~0201X104M6R3NT  [C0201]  146.78 75.35 180 top
CV30  C0201X5R104M6R3NTA~~0201X104M6R3NT  [C0201]  136.74 82.25 0 bottom
CV31  C0201X5R104M6R3NTA~~0201X104M6R3NT  [C0201]  129.33 82.43 0 top
CV32  C0201X7R221K500NTA~~GRM033R71H221KA12D~~CC0201KRX7R9BB221  [C0201]  141.9 49.82 270 top
CV33  C0201X5R104M6R3NTA~~0201X104M6R3NT  [C0201]  142.32 52.27 0 top
CV34  C0201X5R104M6R3NTA~~0201X104M6R3NT  [C0201]  128.34 79.01 180 top
CV35  C0201X5R104M6R3NTA~~0201X104M6R3NT  [C0201]  140.45 85.23 270 bottom
CV36  C0201X5R104M6R3NTA~~0201X104M6R3NT  [C0201]  144.54 51.26 90 top
CV37  C0201X5R104M6R3NTA~~0201X104M6R3NT  [C0201]  139.95 53.97 90 bottom
CV41  C0201X5R104M6R3NTA~~0201X104M6R3NT  [C0201]  145.29 67.61 270 top
CV42  C0201X5R104M6R3NTA~~0201X104M6R3NT  [C0201]  145.84 67.62 270 top
CV43  CL10A226MQ8NRNC~~GRM188R60J226MEA0D~~JDK107BBJ226MA-T~~CC0603MRX5R5BB226  [C0603_L]  134.24 59.64 90 top
CV44  C0402X5R475M6R3NTC~~JMK105BBJ475MV-F+JDK105ABJ475MV~~CC0402MRX5R5BB475~~CL05A475MQ5NRNC~~GRM155R60J475ME87D  [C0402_0D65]  135.51 59.76 90 top
CV45  C0201X5R104M6R3NTA~~0201X104M6R3NT  [C0201]  146.35 69.23 0 top
CV46  C0201X5R104M6R3NTA~~0201X104M6R3NT  [C0201]  150.52 64.16 0 top
CV47  C0201C0G150J250NTA~~GRM0335C1E150JA01D~~CC0201JRNPO8BN150  [C0201]  149.18 54.21 0 bottom
CV48  C0201C0G150J250NTA~~GRM0335C1E150JA01D~~CC0201JRNPO8BN150  [C0201]  148.07 54.21 0 bottom
CV49  CL10A226MQ8NRNC~~GRM188R60J226MEA0D~~JDK107BBJ226MA-T~~CC0603MRX5R5BB226  [C0603_L]  172.92 53.33 270 top
CV50  CL10A226MQ8NRNC~~GRM188R60J226MEA0D~~JDK107BBJ226MA-T~~CC0603MRX5R5BB226  [C0603_L]  171.56 53.33 270 top
CV51  CL10A226MQ8NRNC~~GRM188R60J226MEA0D~~JDK107BBJ226MA-T~~CC0603MRX5R5BB226  [C0603_L]  170.23 53.33 270 top
CV52  C0402X5R106M6R3NTC~~CL05A106MQ5NUNC~~GRM155R60J106ME44~~JMK105CBJ106MV-F  [C0402_0D8]  156.48 69.96 180 top
CV53  C0201X5R105M6R3NTX~~CL03A105MQ3CSNH~~GRM033R60J105MEA2D~~JMK063ABJ105MP+JDK063ABJ105MP~~CC0201MRX5R5BB105  [C0201_0D4]  156.8 73.44 0 top
CV54  C0201X5R105M6R3NTX~~CL03A105MQ3CSNH~~GRM033R60J105MEA2D~~JMK063ABJ105MP+JDK063ABJ105MP~~CC0201MRX5R5BB105  [C0201_0D4]  156.59 74.37 90 top
CV55  C0201X5R105M6R3NTX~~CL03A105MQ3CSNH~~GRM033R60J105MEA2D~~JMK063ABJ105MP+JDK063ABJ105MP~~CC0201MRX5R5BB105  [C0201_0D4]  158.04 75 180 top
CV56  C0201X5R105M6R3NTX~~CL03A105MQ3CSNH~~GRM033R60J105MEA2D~~JMK063ABJ105MP+JDK063ABJ105MP~~CC0201MRX5R5BB105  [C0201_0D4]  156.93 68.61 0 top
CV57  C0201X5R104M6R3NTA~~0201X104M6R3NT  [C0201]  157 67.98 180 top
CV58  C0201X5R104M6R3NTA~~0201X104M6R3NT  [C0201]  156.96 66.17 180 top
CV59  C0402X5R106M6R3NTC~~CL05A106MQ5NUNC~~GRM155R60J106ME44~~JMK105CBJ106MV-F  [C0402_0D8]  157.25 66.92 180 top
CV60  C0402X5R106M6R3NTC~~CL05A106MQ5NUNC~~GRM155R60J106ME44~~JMK105CBJ106MV-F  [C0402_0D8]  155.86 65.5 90 top
CV61  C0201X5R105M6R3NTX~~CL03A105MQ3CSNH~~GRM033R60J105MEA2D~~JMK063ABJ105MP+JDK063ABJ105MP~~CC0201MRX5R5BB105  [C0201_0D4]  154.57 65.38 270 top
CV62  C0201X5R105M6R3NTX~~CL03A105MQ3CSNH~~GRM033R60J105MEA2D~~JMK063ABJ105MP+JDK063ABJ105MP~~CC0201MRX5R5BB105  [C0201_0D4]  153.92 65.35 270 top
CV63  C0201X5R105M6R3NTX~~CL03A105MQ3CSNH~~GRM033R60J105MEA2D~~JMK063ABJ105MP+JDK063ABJ105MP~~CC0201MRX5R5BB105  [C0201_0D4]  151.46 65.16 270 top
CV64  C0201X5R105M6R3NTX~~CL03A105MQ3CSNH~~GRM033R60J105MEA2D~~JMK063ABJ105MP+JDK063ABJ105MP~~CC0201MRX5R5BB105  [C0201_0D4]  156.85 71.42 0 top
CV68  C0402X5R475M6R3NTC~~JMK105BBJ475MV-F+JDK105ABJ475MV~~CC0402MRX5R5BB475~~CL05A475MQ5NRNC~~GRM155R60J475ME87D  [C0402_0D65]  152.25 71.64 270 top
CV69  C0402X5R475M6R3NTC~~JMK105BBJ475MV-F+JDK105ABJ475MV~~CC0402MRX5R5BB475~~CL05A475MQ5NRNC~~GRM155R60J475ME87D  [C0402_0D65]  144.53 72.12 90 top
CV70  C0402X5R475M6R3NTC~~JMK105BBJ475MV-F+JDK105ABJ475MV~~CC0402MRX5R5BB475~~CL05A475MQ5NRNC~~GRM155R60J475ME87D  [C0402_0D65]  154.02 70.08 0 top
CV71  C0402X5R475M6R3NTC~~JMK105BBJ475MV-F+JDK105ABJ475MV~~CC0402MRX5R5BB475~~CL05A475MQ5NRNC~~GRM155R60J475ME87D  [C0402_0D65]  152.24 66.14 270 top
CV72  C0402X5R475M6R3NTC~~JMK105BBJ475MV-F+JDK105ABJ475MV~~CC0402MRX5R5BB475~~CL05A475MQ5NRNC~~GRM155R60J475ME87D  [C0402_0D65]  145.46 72.29 90 top
CV73  C0402X5R475M6R3NTC~~JMK105BBJ475MV-F+JDK105ABJ475MV~~CC0402MRX5R5BB475~~CL05A475MQ5NRNC~~GRM155R60J475ME87D  [C0402_0D65]  143.64 69.67 270 top
CV74  C0402X5R475M6R3NTC~~JMK105BBJ475MV-F+JDK105ABJ475MV~~CC0402MRX5R5BB475~~CL05A475MQ5NRNC~~GRM155R60J475ME87D  [C0402_0D65]  146.38 72.29 90 top
CV75  C0402X5R475M6R3NTC~~JMK105BBJ475MV-F+JDK105ABJ475MV~~CC0402MRX5R5BB475~~CL05A475MQ5NRNC~~GRM155R60J475ME87D  [C0402_0D65]  149.34 67.57 0 top
CV76  C0402X5R475M6R3NTC~~JMK105BBJ475MV-F+JDK105ABJ475MV~~CC0402MRX5R5BB475~~CL05A475MQ5NRNC~~GRM155R60J475ME87D  [C0402_0D65]  152.25 69.59 90 top
CV77  C0402X5R475M6R3NTC~~JMK105BBJ475MV-F+JDK105ABJ475MV~~CC0402MRX5R5BB475~~CL05A475MQ5NRNC~~GRM155R60J475ME87D  [C0402_0D65]  152.25 75.14 90 top
CV78  C0402X5R475M6R3NTC~~JMK105BBJ475MV-F+JDK105ABJ475MV~~CC0402MRX5R5BB475~~CL05A475MQ5NRNC~~GRM155R60J475ME87D  [C0402_0D65]  153.75 75.61 180 top
CV79  C0402X5R475M6R3NTC~~JMK105BBJ475MV-F+JDK105ABJ475MV~~CC0402MRX5R5BB475~~CL05A475MQ5NRNC~~GRM155R60J475ME87D  [C0402_0D65]  154.2 67.59 180 top
CV80  C0201X5R105M6R3NTX~~CL03A105MQ3CSNH~~GRM033R60J105MEA2D~~JMK063ABJ105MP+JDK063ABJ105MP~~CC0201MRX5R5BB105  [C0201_0D4]  154.17 66.88 0 top
CV81  C0201X5R105M6R3NTX~~CL03A105MQ3CSNH~~GRM033R60J105MEA2D~~JMK063ABJ105MP+JDK063ABJ105MP~~CC0201MRX5R5BB105  [C0201_0D4]  149.08 72.91 270 top
CV82  C0201X5R105M6R3NTX~~CL03A105MQ3CSNH~~GRM033R60J105MEA2D~~JMK063ABJ105MP+JDK063ABJ105MP~~CC0201MRX5R5BB105  [C0201_0D4]  144.65 74.32 270 top
CV83  C0201X5R105M6R3NTX~~CL03A105MQ3CSNH~~GRM033R60J105MEA2D~~JMK063ABJ105MP+JDK063ABJ105MP~~CC0201MRX5R5BB105  [C0201_0D4]  153.93 72.85 270 top
CV84  C0201X5R105M6R3NTX~~CL03A105MQ3CSNH~~GRM033R60J105MEA2D~~JMK063ABJ105MP+JDK063ABJ105MP~~CC0201MRX5R5BB105  [C0201_0D4]  149.61 72.92 270 top
CV85  C0201C0G330J250NTA+C0201C0G330J250NJA~~GRM0335C1E330JD01~~CC0201JRNPO8BN330  [C0201]  154.18 68.34 180 top
CV86  C0402X5R106M6R3NTC~~CL05A106MQ5NUNC~~GRM155R60J106ME44~~JMK105CBJ106MV-F  [C0402_0D8]  133.22 74.11 90 top
CV87  C0402X5R106M6R3NTC~~CL05A106MQ5NUNC~~GRM155R60J106ME44~~JMK105CBJ106MV-F  [C0402_0D8]  135.25 65.1 0 top
CV88  C0402X5R106M6R3NTC~~CL05A106MQ5NUNC~~GRM155R60J106ME44~~JMK105CBJ106MV-F  [C0402_0D8]  150.83 75.61 180 top
CV89  C0402X5R106M6R3NTC~~CL05A106MQ5NUNC~~GRM155R60J106ME44~~JMK105CBJ106MV-F  [C0402_0D8]  143.89 74.5 90 top
CV90  C0402X5R106M6R3NTC~~CL05A106MQ5NUNC~~GRM155R60J106ME44~~JMK105CBJ106MV-F  [C0402_0D8]  147.25 70.08 0 top
CV91  C0402X5R106M6R3NTC~~CL05A106MQ5NUNC~~GRM155R60J106ME44~~JMK105CBJ106MV-F  [C0402_0D8]  134.24 74.11 90 top
CV92  C0402X5R106M6R3NTC~~CL05A106MQ5NUNC~~GRM155R60J106ME44~~JMK105CBJ106MV-F  [C0402_0D8]  152.25 67.87 90 top
CV93  C0402X5R106M6R3NTC~~CL05A106MQ5NUNC~~GRM155R60J106ME44~~JMK105CBJ106MV-F  [C0402_0D8]  135.4 74.12 90 bottom
CV94  C0402X5R106M6R3NTC~~CL05A106MQ5NUNC~~GRM155R60J106ME44~~JMK105CBJ106MV-F  [C0402_0D8]  148.92 75.61 180 top
CV95  C0402X5R106M6R3NTC~~CL05A106MQ5NUNC~~GRM155R60J106ME44~~JMK105CBJ106MV-F  [C0402_0D8]  137.03 64.46 270 bottom
CV96  C0402X5R106M6R3NTC~~CL05A106MQ5NUNC~~GRM155R60J106ME44~~JMK105CBJ106MV-F  [C0402_0D8]  136.34 74.12 90 bottom
CV97  C0402X5R475M6R3NTC~~JMK105BBJ475MV-F+JDK105ABJ475MV~~CC0402MRX5R5BB475~~CL05A475MQ5NRNC~~GRM155R60J475ME87D  [C0402_0D65]  148.97 70.08 180 top
CV98  C0402X5R475M6R3NTC~~JMK105BBJ475MV-F+JDK105ABJ475MV~~CC0402MRX5R5BB475~~CL05A475MQ5NRNC~~GRM155R60J475ME87D  [C0402_0D65]  146.59 67.66 270 top
CV99  C0201C0G330J250NTA+C0201C0G330J250NJA~~GRM0335C1E330JD01~~CC0201JRNPO8BN330  [C0201]  149.26 68.51 0 top
CV100  C0402X5R475M6R3NTC~~JMK105BBJ475MV-F+JDK105ABJ475MV~~CC0402MRX5R5BB475~~CL05A475MQ5NRNC~~GRM155R60J475ME87D  [C0402_0D65]  152.25 73.36 270 top
CV101  C0402X5R475M6R3NTC~~JMK105BBJ475MV-F+JDK105ABJ475MV~~CC0402MRX5R5BB475~~CL05A475MQ5NRNC~~GRM155R60J475ME87D  [C0402_0D65]  155.04 73.32 180 top
CV102  CL10A226MQ8NRNC~~GRM188R60J226MEA0D~~JDK107BBJ226MA-T~~CC0603MRX5R5BB226  [C0603_L]  134.87 61.54 0 top
CV103  CL10A226MQ8NRNC~~GRM188R60J226MEA0D~~JDK107BBJ226MA-T~~CC0603MRX5R5BB226  [C0603_L]  135.63 64.34 270 bottom
CV104  CL10A226MQ8NRNC~~GRM188R60J226MEA0D~~JDK107BBJ226MA-T~~CC0603MRX5R5BB226  [C0603_L]  135 63.83 0 top
CV105  CL10A226MQ8NRNC~~GRM188R60J226MEA0D~~JDK107BBJ226MA-T~~CC0603MRX5R5BB226  [C0603_L]  134.24 64.34 270 bottom
CV106  C0201X5R104M6R3NTA~~0201X104M6R3NT  [C0201]  146.95 65.12 90 top
CV107  C0201X5R104M6R3NTA~~0201X104M6R3NT  [C0201]  147.48 65.13 90 top
CV108  C0201X5R105M6R3NTX~~CL03A105MQ3CSNH~~GRM033R60J105MEA2D~~JMK063ABJ105MP+JDK063ABJ105MP~~CC0201MRX5R5BB105  [C0201_0D4]  146.41 65.12 270 top
CV109  C0201X5R104M6R3NTA~~0201X104M6R3NT  [C0201]  149.34 65.16 90 top
CV110  C0201X5R104M6R3NTA~~0201X104M6R3NT  [C0201]  150.3 65.25 0 top
CV111  C0201X5R105M6R3NTX~~CL03A105MQ3CSNH~~GRM033R60J105MEA2D~~JMK063ABJ105MP+JDK063ABJ105MP~~CC0201MRX5R5BB105  [C0201_0D4]  150.3 64.72 180 top
CV112  C0402X5R475M6R3NTC~~JMK105BBJ475MV-F+JDK105ABJ475MV~~CC0402MRX5R5BB475~~CL05A475MQ5NRNC~~GRM155R60J475ME87D  [C0402_0D65]  153.89 53.32 270 bottom
CV113  C0402X5R475M6R3NTC~~JMK105BBJ475MV-F+JDK105ABJ475MV~~CC0402MRX5R5BB475~~CL05A475MQ5NRNC~~GRM155R60J475ME87D  [C0402_0D65]  145.68 65.42 90 top
CV114  CL10A226MQ8NRNC~~GRM188R60J226MEA0D~~JDK107BBJ226MA-T~~CC0603MRX5R5BB226  [C0603_L]  157.58 85.71 180 bottom
CV115  C0201X5R105M6R3NTX~~CL03A105MQ3CSNH~~GRM033R60J105MEA2D~~JMK063ABJ105MP+JDK063ABJ105MP~~CC0201MRX5R5BB105  [C0201_0D4]  158.04 65.65 180 top
CV116  C0201X5R104M6R3NTA~~0201X104M6R3NT  [C0201]  158.58 70.6 0 top
CV117  C0201X5R104M6R3NTA~~0201X104M6R3NT  [C0201]  153 63.75 180 top
CV118  CC0201KBX7R8BB821~~C0201X7R821K250NTA//CC0201KBX7R8BB821  [C0201]  180.65 91.46 180 bottom
CV119  CC0201KBX7R8BB821~~C0201X7R821K250NTA//CC0201KBX7R8BB821  [C0201]  182.19 59.69 0 top
CV120  C0201X7R103K160NTA+C0201X7R103K160NJA~~GRM033R71C103KA01D~~CC0201KRX7R7BB103  [C0201]  179.78 59 90 top
CV121  C0201X7R103K160NTA+C0201X7R103K160NJA~~GRM033R71C103KA01D~~CC0201KRX7R7BB103  [C0201]  179.96 89.48 270 top
CV122  C0402X5R106M6R3NTC~~CL05A106MQ5NUNC~~GRM155R60J106ME44~~JMK105CBJ106MV-F  [C0402_0D8]  174.69 71.38 180 top
CV123  C0402X5R106M6R3NTC~~CL05A106MQ5NUNC~~GRM155R60J106ME44~~JMK105CBJ106MV-F  [C0402_0D8]  177.81 71.41 180 top
CV124  C0201X5R105M6R3NTX~~CL03A105MQ3CSNH~~GRM033R60J105MEA2D~~JMK063ABJ105MP+JDK063ABJ105MP~~CC0201MRX5R5BB105  [C0201_0D4]  176.88 57.47 90 bottom
CV125  C0201X5R105M6R3NTX~~CL03A105MQ3CSNH~~GRM033R60J105MEA2D~~JMK063ABJ105MP+JDK063ABJ105MP~~CC0201MRX5R5BB105  [C0201_0D4]  186.58 66.13 180 top
CV126  C0201X5R105M6R3NTX~~CL03A105MQ3CSNH~~GRM033R60J105MEA2D~~JMK063ABJ105MP+JDK063ABJ105MP~~CC0201MRX5R5BB105  [C0201_0D4]  185.88 64.17 180 top
CV127  C0201X5R105M6R3NTX~~CL03A105MQ3CSNH~~GRM033R60J105MEA2D~~JMK063ABJ105MP+JDK063ABJ105MP~~CC0201MRX5R5BB105  [C0201_0D4]  176.16 71.24 0 top
CV128  C0201X5R105M6R3NTX~~CL03A105MQ3CSNH~~GRM033R60J105MEA2D~~JMK063ABJ105MP+JDK063ABJ105MP~~CC0201MRX5R5BB105  [C0201_0D4]  187.62 61.43 270 top
CV129  C0201X5R105M6R3NTX~~CL03A105MQ3CSNH~~GRM033R60J105MEA2D~~JMK063ABJ105MP+JDK063ABJ105MP~~CC0201MRX5R5BB105  [C0201_0D4]  183.42 66.11 0 top
CV130  C0201X5R105M6R3NTX~~CL03A105MQ3CSNH~~GRM033R60J105MEA2D~~JMK063ABJ105MP+JDK063ABJ105MP~~CC0201MRX5R5BB105  [C0201_0D4]  187.41 71.29 180 top
CV131  C0201X5R105M6R3NTX~~CL03A105MQ3CSNH~~GRM033R60J105MEA2D~~JMK063ABJ105MP+JDK063ABJ105MP~~CC0201MRX5R5BB105  [C0201_0D4]  185.02 71.34 0 top
CV132  C0201C0G330J250NTA+C0201C0G330J250NJA~~GRM0335C1E330JD01~~CC0201JRNPO8BN330  [C0201]  178.78 91.73 90 bottom
CV133  C0201C0G330J250NTA+C0201C0G330J250NJA~~GRM0335C1E330JD01~~CC0201JRNPO8BN330  [C0201]  177.64 91.73 90 bottom
CV134  CL10A226MQ8NRNC~~GRM188R60J226MEA0D~~JDK107BBJ226MA-T~~CC0603MRX5R5BB226  [C0603_L]  187.42 74.95 180 bottom
CV135  CL10A226MQ8NRNC~~GRM188R60J226MEA0D~~JDK107BBJ226MA-T~~CC0603MRX5R5BB226  [C0603_L]  185.42 76.4 270 bottom
CV136  CL10A226MQ8NRNC~~GRM188R60J226MEA0D~~JDK107BBJ226MA-T~~CC0603MRX5R5BB226  [C0603_L]  184.02 76.4 270 bottom
CV137  CL10A226MQ8NRNC~~GRM188R60J226MEA0D~~JDK107BBJ226MA-T~~CC0603MRX5R5BB226  [C0603_L]  182.62 76.4 270 bottom
CV138  CL10A226MQ8NRNC~~GRM188R60J226MEA0D~~JDK107BBJ226MA-T~~CC0603MRX5R5BB226  [C0603_L]  185.42 73.48 90 bottom
CV139  C0201X5R105M6R3NTX~~CL03A105MQ3CSNH~~GRM033R60J105MEA2D~~JMK063ABJ105MP+JDK063ABJ105MP~~CC0201MRX5R5BB105  [C0201_0D4]  185.5 57.5 90 bottom
CV140  C0201X5R105M6R3NTX~~CL03A105MQ3CSNH~~GRM033R60J105MEA2D~~JMK063ABJ105MP+JDK063ABJ105MP~~CC0201MRX5R5BB105  [C0201_0D4]  178.05 57.47 90 bottom
CV141  C0201X5R105M6R3NTX~~CL03A105MQ3CSNH~~GRM033R60J105MEA2D~~JMK063ABJ105MP+JDK063ABJ105MP~~CC0201MRX5R5BB105  [C0201_0D4]  185.47 58.57 270 top
CV142  C0201X5R105M6R3NTX~~CL03A105MQ3CSNH~~GRM033R60J105MEA2D~~JMK063ABJ105MP+JDK063ABJ105MP~~CC0201MRX5R5BB105  [C0201_0D4]  177.46 57.47 90 bottom
CV143  C0201X5R105M6R3NTX~~CL03A105MQ3CSNH~~GRM033R60J105MEA2D~~JMK063ABJ105MP+JDK063ABJ105MP~~CC0201MRX5R5BB105  [C0201_0D4]  182.95 63.99 0 top
CV144  C0201X5R105M6R3NTX~~CL03A105MQ3CSNH~~GRM033R60J105MEA2D~~JMK063ABJ105MP+JDK063ABJ105MP~~CC0201MRX5R5BB105  [C0201_0D4]  182.2 57.63 90 bottom
CV145  C0402X5R106M6R3NTC~~CL05A106MQ5NUNC~~GRM155R60J106ME44~~JMK105CBJ106MV-F  [C0402_0D8]  184.97 91.61 180 bottom
CV146  C0402X5R106M6R3NTC~~CL05A106MQ5NUNC~~GRM155R60J106ME44~~JMK105CBJ106MV-F  [C0402_0D8]  177.79 77.97 0 top
CV147  C0201X5R105M6R3NTX~~CL03A105MQ3CSNH~~GRM033R60J105MEA2D~~JMK063ABJ105MP+JDK063ABJ105MP~~CC0201MRX5R5BB105  [C0201_0D4]  178.21 91.73 270 bottom
CV148  C0201X5R105M6R3NTX~~CL03A105MQ3CSNH~~GRM033R60J105MEA2D~~JMK063ABJ105MP+JDK063ABJ105MP~~CC0201MRX5R5BB105  [C0201_0D4]  186.65 85.52 180 top
CV149  C0201X5R105M6R3NTX~~CL03A105MQ3CSNH~~GRM033R60J105MEA2D~~JMK063ABJ105MP+JDK063ABJ105MP~~CC0201MRX5R5BB105  [C0201_0D4]  177.08 91.73 270 bottom
CV150  C0201X5R105M6R3NTX~~CL03A105MQ3CSNH~~GRM033R60J105MEA2D~~JMK063ABJ105MP+JDK063ABJ105MP~~CC0201MRX5R5BB105  [C0201_0D4]  177.35 90.84 180 top
CV151  C0201X5R105M6R3NTX~~CL03A105MQ3CSNH~~GRM033R60J105MEA2D~~JMK063ABJ105MP+JDK063ABJ105MP~~CC0201MRX5R5BB105  [C0201_0D4]  183.8 86.3 180 top
CV152  C0201X5R105M6R3NTX~~CL03A105MQ3CSNH~~GRM033R60J105MEA2D~~JMK063ABJ105MP+JDK063ABJ105MP~~CC0201MRX5R5BB105  [C0201_0D4]  182.07 78.03 0 top
CV153  C0201X5R105M6R3NTX~~CL03A105MQ3CSNH~~GRM033R60J105MEA2D~~JMK063ABJ105MP+JDK063ABJ105MP~~CC0201MRX5R5BB105  [C0201_0D4]  182.44 81.47 270 top
CV154  C0201X5R105M6R3NTX~~CL03A105MQ3CSNH~~GRM033R60J105MEA2D~~JMK063ABJ105MP+JDK063ABJ105MP~~CC0201MRX5R5BB105  [C0201_0D4]  182.45 91.7 270 bottom
CV155  CL10A226MQ8NRNC~~GRM188R60J226MEA0D~~JDK107BBJ226MA-T~~CC0603MRX5R5BB226  [C0603_L]  185.86 92.11 90 top
CV156  CL10A226MQ8NRNC~~GRM188R60J226MEA0D~~JDK107BBJ226MA-T~~CC0603MRX5R5BB226  [C0603_L]  184.02 73.48 90 bottom
CV157  CL10A226MQ8NRNC~~GRM188R60J226MEA0D~~JDK107BBJ226MA-T~~CC0603MRX5R5BB226  [C0603_L]  175.7 75.98 0 top
CV158  CL10A226MQ8NRNC~~GRM188R60J226MEA0D~~JDK107BBJ226MA-T~~CC0603MRX5R5BB226  [C0603_L]  182.62 73.48 90 bottom
CV159  CL10A226MQ8NRNC~~GRM188R60J226MEA0D~~JDK107BBJ226MA-T~~CC0603MRX5R5BB226  [C0603_L]  178.11 75.98 180 top
CV160  C0201X5R105M6R3NTX~~CL03A105MQ3CSNH~~GRM033R60J105MEA2D~~JMK063ABJ105MP+JDK063ABJ105MP~~CC0201MRX5R5BB105  [C0201_0D4]  183.04 91.7 270 bottom
CV161  C0201X5R105M6R3NTX~~CL03A105MQ3CSNH~~GRM033R60J105MEA2D~~JMK063ABJ105MP+JDK063ABJ105MP~~CC0201MRX5R5BB105  [C0201_0D4]  174.58 78.2 0 top
CV162  C0201X5R105M6R3NTX~~CL03A105MQ3CSNH~~GRM033R60J105MEA2D~~JMK063ABJ105MP+JDK063ABJ105MP~~CC0201MRX5R5BB105  [C0201_0D4]  185.86 78.53 180 top
CV163  C0201X5R105M6R3NTX~~CL03A105MQ3CSNH~~GRM033R60J105MEA2D~~JMK063ABJ105MP+JDK063ABJ105MP~~CC0201MRX5R5BB105  [C0201_0D4]  185.86 79.11 180 top
CV164  C0201X5R105M6R3NTX~~CL03A105MQ3CSNH~~GRM033R60J105MEA2D~~JMK063ABJ105MP+JDK063ABJ105MP~~CC0201MRX5R5BB105  [C0201_0D4]  176.49 91.73 270 bottom
CV165  C0201X5R105M6R3NTX~~CL03A105MQ3CSNH~~GRM033R60J105MEA2D~~JMK063ABJ105MP+JDK063ABJ105MP~~CC0201MRX5R5BB105  [C0201_0D4]  175.32 90.84 0 top
CV166  C0201X5R105M6R3NTX~~CL03A105MQ3CSNH~~GRM033R60J105MEA2D~~JMK063ABJ105MP+JDK063ABJ105MP~~CC0201MRX5R5BB105  [C0201_0D4]  184.93 57.5 90 bottom
CV167  C0201X5R105M6R3NTX~~CL03A105MQ3CSNH~~GRM033R60J105MEA2D~~JMK063ABJ105MP+JDK063ABJ105MP~~CC0201MRX5R5BB105  [C0201_0D4]  176.29 57.47 90 bottom
CV168  C0201X5R105M6R3NTX~~CL03A105MQ3CSNH~~GRM033R60J105MEA2D~~JMK063ABJ105MP+JDK063ABJ105MP~~CC0201MRX5R5BB105  [C0201_0D4]  186.07 57.5 90 bottom
CV169  C0201X5R105M6R3NTX~~CL03A105MQ3CSNH~~GRM033R60J105MEA2D~~JMK063ABJ105MP+JDK063ABJ105MP~~CC0201MRX5R5BB105  [C0201_0D4]  187.14 58.67 270 top
CV170  C0402X5R106M6R3NTC~~CL05A106MQ5NUNC~~GRM155R60J106ME44~~JMK105CBJ106MV-F  [C0402_0D8]  173.9 59.55 180 top
CV171  C0402X5R106M6R3NTC~~CL05A106MQ5NUNC~~GRM155R60J106ME44~~JMK105CBJ106MV-F  [C0402_0D8]  176.24 59.49 180 top
CV174  C0201X5R105M6R3NTX~~CL03A105MQ3CSNH~~GRM033R60J105MEA2D~~JMK063ABJ105MP+JDK063ABJ105MP~~CC0201MRX5R5BB105  [C0201_0D4]  182.77 91.85 270 top
CV175  C0201X5R105M6R3NTX~~CL03A105MQ3CSNH~~GRM033R60J105MEA2D~~JMK063ABJ105MP+JDK063ABJ105MP~~CC0201MRX5R5BB105  [C0201_0D4]  183.41 91.85 270 top
CV176  C0201X5R105M6R3NTX~~CL03A105MQ3CSNH~~GRM033R60J105MEA2D~~JMK063ABJ105MP+JDK063ABJ105MP~~CC0201MRX5R5BB105  [C0201_0D4]  176.17 78.2 0 top
CV177  C0201X5R105M6R3NTX~~CL03A105MQ3CSNH~~GRM033R60J105MEA2D~~JMK063ABJ105MP+JDK063ABJ105MP~~CC0201MRX5R5BB105  [C0201_0D4]  183.98 91.85 270 top
CV178  C0402X5R106M6R3NTC~~CL05A106MQ5NUNC~~GRM155R60J106ME44~~JMK105CBJ106MV-F  [C0402_0D8]  186.5 83.6 0 top
CV179  C0402X5R106M6R3NTC~~CL05A106MQ5NUNC~~GRM155R60J106ME44~~JMK105CBJ106MV-F  [C0402_0D8]  184.72 91.99 90 top
CV187  C0201X5R104M6R3NTA~~0201X104M6R3NT  [C0201]  153.29 65.35 90 top
CV192  C0201X5R105M6R3NTX~~CL03A105MQ3CSNH~~GRM033R60J105MEA2D~~JMK063ABJ105MP+JDK063ABJ105MP~~CC0201MRX5R5BB105  [C0201_0D4]  137.74 52.61 180 bottom
CV193  C0201C0G101J500NTA~~GRM0335C1H101JA01D~~CC0201JRNPO9BN101  [C0201]  142.92 52.51 270 bottom
CV194  C0201C0G101J500NTA~~GRM0335C1H101JA01D~~CC0201JRNPO9BN101  [C0201]  146.05 50.61 270 bottom
CV195  cap  [C0201]  149.58 84.91 270 bottom
CV196  CAP  [C0201]  143.82 51.27 270 top
CV197  C0402X5R475M6R3NTC~~JMK105BBJ475MV-F+JDK105ABJ475MV~~CC0402MRX5R5BB475~~CL05A475MQ5NRNC~~GRM155R60J475ME87D  [C0402_0D65]  152.03 77.9 90 top
CV198  C0402X5R475M6R3NTC~~JMK105BBJ475MV-F+JDK105ABJ475MV~~CC0402MRX5R5BB475~~CL05A475MQ5NRNC~~GRM155R60J475ME87D  [C0402_0D65]  152.98 77.89 90 top
CV199  C0201X5R223K6R3NTA~~GRM033R60J223KE01D~~CC0201KRX5R5BB223  [C0201]  137.72 50.82 0 bottom
CV200  C0201X5R104M6R3NTA~~0201X104M6R3NT  [C0201]  148.8 65.16 90 top
CV201  GRM155R60J225KE95~~CL05A225KQ5NNNC  [C0402]  144.24 65.25 180 top
CV202  C0201C0G470J250NTA~~GRM0335C1E470JD01D~~CC0201JRNPO8BN470  [C0201]  148.21 65.15 90 top
CV203  C0201C0G470J250NTA~~GRM0335C1E470JD01D~~CC0201JRNPO8BN470  [C0201]  157.72 86.71 180 bottom
CV204  GRM155R60J225KE95~~CL05A225KQ5NNNC  [C0402]  152.93 53.36 270 bottom
CV205  CC0201JRNPO9BN220~~C0201C0G220J500NTA  [C0201]  157.4 79.3 135 top
CV206  CC0201JRNPO9BN220~~C0201C0G220J500NTA  [C0201]  157.78 79.68 135 top
CV207  CC0201JRNPO9BN220~~C0201C0G220J500NTA  [C0201]  165.48 88.34 0 top
CV208  CC0201JRNPO9BN220~~C0201C0G220J500NTA  [C0201]  165.48 88.85 0 top
CV209  CC0201JRNPO9BN220~~C0201C0G220J500NTA  [C0201]  149.86 66.11 270 top
CW3  C0402X5R106M6R3NTC~~CL05A106MQ5NUNC~~GRM155R60J106ME44~~JMK105CBJ106MV-F  [C0402_0D8]  153.72 12.16 0 top
CW4  C0201X7R103K160NTA+C0201X7R103K160NJA~~GRM033R71C103KA01D~~CC0201KRX7R7BB103  [C0201]  153.92 14.04 0 top
CW5  C0201X5R104M6R3NTA~~0201X104M6R3NT  [C0201]  153.92 12.93 180 top
CW6  C0201C0G330J250NTA+C0201C0G330J250NJA~~GRM0335C1E330JD01~~CC0201JRNPO8BN330  [C0201]  153.92 13.48 180 top
CW8  CC0201JRNPO8BN220~~GRM0335C1E220JD01  [C0201]  151.08 18.56 180 top
CW9  C0201X5R104M6R3NTA~~0201X104M6R3NT  [C0201]  143.56 21.16 0 bottom
CW10  C0201X5R104M6R3NTA~~0201X104M6R3NT  [C0201]  143.56 21.77 0 bottom
CW11  C0402X5R106M6R3NTC~~CL05A106MQ5NUNC~~GRM155R60J106ME44~~JMK105CBJ106MV-F  [C0402_0D8]  154.48 28.42 0 top
CW12  C0201X7R103K160NTA+C0201X7R103K160NJA~~GRM033R71C103KA01D~~CC0201KRX7R7BB103  [C0201]  154.43 29.23 0 top
CW13  C0201X5R104M6R3NTA~~0201X104M6R3NT  [C0201]  154.43 30.35 180 top
CW14  C0201C0G330J250NTA+C0201C0G330J250NJA~~GRM0335C1E330JD01~~CC0201JRNPO8BN330  [C0201]  154.43 29.79 180 top
CW15  C0201X5R104K6R3NTA+C0201X5R104K6R3NJA~~GRM033R60J104KE19D~~CC0201KRX5R5BB104  [C0201]  151.08 18.01 180 top
CW16  cap  [C0201]  151.33 28.67 0 top
CX1  C0201X5R104M6R3NTA~~0201X104M6R3NT  [C0201]  32.79 71.5 90 bottom
CX2  C0201X5R104M6R3NTA~~0201X104M6R3NT  [C0201]  32.28 71.5 90 bottom
CX3  C0402X5R106M6R3NTC~~CL05A106MQ5NUNC~~GRM155R60J106ME44~~JMK105CBJ106MV-F  [C0402_0D8]  22.99 72.34 0 top
CX4  C0201X5R105M6R3NTX~~CL03A105MQ3CSNH~~GRM033R60J105MEA2D~~JMK063ABJ105MP+JDK063ABJ105MP~~CC0201MRX5R5BB105  [C0201_0D4]  20.83 75 90 top
CX5  C0201X5R104M6R3NTA~~0201X104M6R3NT  [C0201]  31.32 71.5 90 bottom
CX6  C0201X5R104M6R3NTA~~0201X104M6R3NT  [C0201]  30.81 71.5 90 bottom
CX7  C0201X5R104M6R3NTA~~0201X104M6R3NT  [C0201]  29.84 71.5 90 bottom
CX8  C0201X5R104M6R3NTA~~0201X104M6R3NT  [C0201]  29.34 71.5 90 bottom
CX9  C0201X5R104M6R3NTA~~0201X104M6R3NT  [C0201]  19.43 73.1 180 bottom
CX10  C0201C0G470J250NTA~~GRM0335C1E470JD01D~~CC0201JRNPO8BN470  [C0201]  22.86 74.11 0 top
CX13  C0402X5R106M6R3NTC~~CL05A106MQ5NUNC~~GRM155R60J106ME44~~JMK105CBJ106MV-F  [C0402_0D8]  26.49 68.07 90 bottom
CX14  C0402X5R106M6R3NTC~~CL05A106MQ5NUNC~~GRM155R60J106ME44~~JMK105CBJ106MV-F  [C0402_0D8]  22.99 73.35 0 top
CX15  C0201X5R104M6R3NTA~~0201X104M6R3NT  [C0201]  21.46 75 270 top
CX16  C0603X5R475K250NTK~~CL10A475KA8NQNC~~GRM188R61E475KE15D~~TMK107BBJ475KA-T  [C0603]  15.54 71.42 180 top
CX17  C0603X5R106M250NTK~~CL10A106MA8NRNC~~GRM188R61E106MA73D~~TMK107BBJ106MA  [C0603_L]  15.49 72.67 180 top
CX18  C0201X5R104M250NTJ  [C0201]  15.52 70.51 180 top
CX21  C0201X5R104M6R3NTA~~0201X104M6R3NT  [C0201]  21.21 76.32 180 top
CX22  C0201X5R104M6R3NTA~~0201X104M6R3NT  [C0201]  27.3 72.72 0 bottom
CX284  C0603X5R106M250NTK~~CL10A106MA8NRNC~~GRM188R61E106MA73D~~TMK107BBJ106MA  [C0603_L]  23.37 78.46 0 top
CX885  CC0201KRX5R7BB104~~C0201X5R104M160NTA  [C0201]  24.13 82.12 90 top
CX886  C0201X7R103K160NTA+C0201X7R103K160NJA~~GRM033R71C103KA01D~~CC0201KRX7R7BB103  [C0201]  24.64 82.12 270 top
CX887  C0201X5R104K6R3NTA+C0201X5R104K6R3NJA~~GRM033R60J104KE19D~~CC0201KRX5R5BB104  [C0201]  23.11 76.73 0 top
CX888  C0201X5R104M6R3NTA~~0201X104M6R3NT  [C0201]  33.75 71.5 90 bottom
CX889  C0201X5R104M6R3NTA~~0201X104M6R3NT  [C0201]  35.69 71.5 90 bottom
CX890  C0201X5R104M6R3NTA~~0201X104M6R3NT  [C0201]  35.18 71.5 90 bottom
CX891  C0201X5R104M6R3NTA~~0201X104M6R3NT  [C0201]  34.26 71.5 90 bottom
CX892  C0201X5R104M6R3NTA~~0201X104M6R3NT  [C0201]  158.32 90.88 270 bottom
CX893  C0201C0G270J250NTA~~GRM0335C1E270JD01D~~CC0201JRNPO8BN270  [C0201]  25.14 76.02 0 top
CX894  C0201C0G270J250NTA~~GRM0335C1E270JD01D~~CC0201JRNPO8BN270  [C0201]  153.52 87.4 270 bottom
CX895  LMK105BJ225MV-F~~CL05A225MP5NNNC~~GRM155R61A225ME95~~C0402X5R225M100NTB  [C0402_0D55]  20.95 77.01 0 top
CX896  LMK105BJ225MV-F~~CL05A225MP5NNNC~~GRM155R61A225ME95~~C0402X5R225M100NTB  [C0402_0D55]  159 90.86 90 bottom
CX897  cap  [C0201]  23.87 73.23 180 bottom
CX898  cap  [C0201]  24.89 73.23 0 bottom
DA2  LBAT54AWT1G  [NB_SOT323_2D4X2D2X1]  164.74 27.91 180 top
